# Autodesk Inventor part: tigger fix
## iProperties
Created: 2006-04
Part Number: tigger fix
Document SubType Name: Modeling
Designer: Калинин
Author: Калинин
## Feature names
1. Выдавливание1 [Extrusion]
2. Вращение1 [Revolution]
3. Вращение2 [Revolution]
4. Разделение1
5. Сопряжение1 [Fillet]
6. Разделение2
7. Сопряжение2 [Fillet]
